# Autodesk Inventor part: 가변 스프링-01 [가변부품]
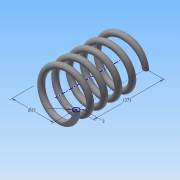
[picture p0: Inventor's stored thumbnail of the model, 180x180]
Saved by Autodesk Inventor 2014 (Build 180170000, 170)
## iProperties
Created: 2015-09
Part Number: 가변 스프링-01 [가변부품]
Material: 강철, 탄소
Document SubType Name: Modeling
Designer: study
Density: 7.87 g/cm^3
Appearance: 반연마
Mass: 18.9154 g
Surface Area: 32.5802 cm^2
Volume: 2.40348 cm^3
Author: study
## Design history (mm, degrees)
sketch "스케치1"
  geometry: L1 (0, 0)-(11, 0); L2 (11, 0)-(11, 40.095); L3 (11, 40.095)-(0, 40.095); L4 (0, 40.095)-(0, 0); C1 r 1.5 at (11, 0)
  constraints: 8 end point, 2 parallel, 1 centre point, 1 coincident, 1 horizontal, 1 perpendicular
  dimensions: "d0" = 3 diameter of C1; "d1" = 40.0955 distance between parallel lines of L3 L1 (derived); "d2" = 22 diameter of L2 L4
feature "코일1" sketch "스케치1" pitch "d3" = 10; turns "d5" = 5; dims "d4" = 40.0955 (= d1), "d6" = 0, angle "d7" = 90 deg, angle "d8" = 90 deg, "d9" = 0, "d10" = 0
node "작업 평면1"
sketch "스케치2"
  geometry: L1 (-12.5, 0)-(-9.5, 0) reference; 1 further point
  constraints: 1 horizontal alignment
extrude "돌출1" cut sketch "스케치2" stored distance "d12" = 10; taper "d13" = 0 deg
node "작업 평면2"
sketch "스케치3"
  geometry: L1 (-9.5, 0)-(-12.5, 0) reference; 1 further point
  constraints: 1 horizontal alignment
extrude "돌출2" cut sketch "스케치3" stored distance "d15" = 10; taper "d16" = 0 deg
node "솔리드1"
node "절단 모서리 투영1"
node "절단 모서리 투영2"
other parameters: "d11" = 0, "d14" = 40.0955 (= d1)
